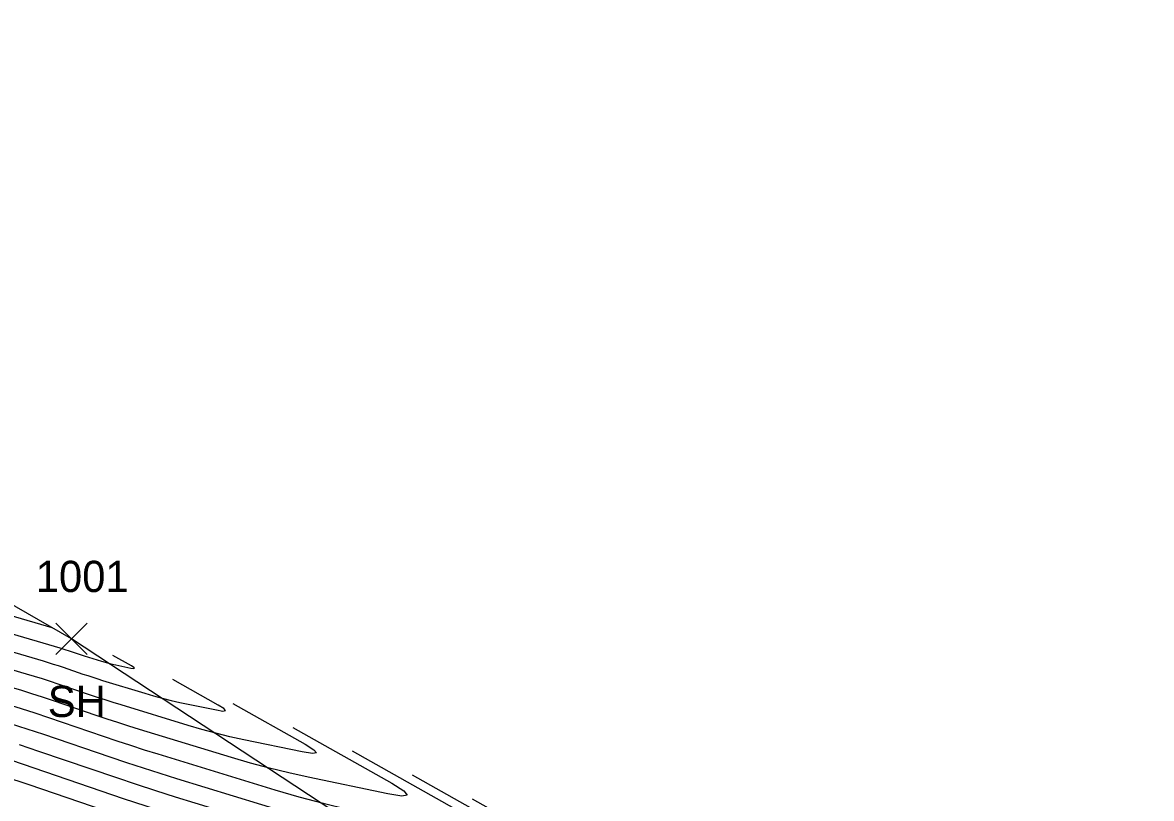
# Model space of a CAD drawing. Extents: x 1650836 to 1652450, y 332578 to 333908.
# Drawn here: x 1651914.6 to 1651986.8, y 332944.5 to 332994.2 of the extents above; entities that cross this region are included whole.
import ezdxf

# ---------------------------------------------------------------- set-up
doc = ezdxf.new("R2010")
doc.units = 0
for name, color, linetype in [('L_A', 7, 'Continuous'), ('L_I', 7, 'Continuous'), ('L_TIC', 7, 'Continuous'), ('LSOGCMA', 7, 'Continuous'), ('LSOGCMI', 7, 'Continuous'), ('LSOGP', 7, 'Continuous')]:
    doc.layers.add(name, color=color, linetype=linetype)

msp = doc.modelspace()

# ---------------------------------------------------------------- linework, layer by layer
at = {"layer": 'L_TIC'}
for points in [[(1651916.714, 332953.706), (1651918.714, 332955.706)], [(1651918.714, 332953.706), (1651916.714, 332955.706)]]:
    msp.add_lwpolyline(points, dxfattribs=at)
at = {"layer": 'LSOGCMA'}
msp.add_lwpolyline([(1651928.045, 332950.575), (1651932.669, 332947.971), (1651933.235, 332947.614), (1651933.392, 332947.411), (1651933.14, 332947.362), (1651932.479, 332947.466), (1651928.759, 332948.246), (1651927.858, 332948.446), (1651926.961, 332948.666), (1651926.069, 332948.906), (1651925.183, 332949.166), (1651920.894, 332950.478), (1651920.388, 332950.635), (1651919.883, 332950.797), (1651919.379, 332950.962), (1651918.877, 332951.131), (1651916.87, 332951.816), (1651916.368, 332951.985), (1651915.863, 332952.148), (1651915.357, 332952.305), (1651914.849, 332952.458), (1651901.898, 332956.265)], dxfattribs=at)
at = {"layer": 'LSOGCMI'}
for points in [[(1651813.439, 332994.157), (1651846.906, 332980.116), (1651850.563, 332978.602), (1651854.233, 332977.123), (1651857.916, 332975.677), (1651861.613, 332974.266), (1651881.787, 332966.674), (1651882.811, 332966.285), (1651883.833, 332965.891), (1651884.852, 332965.49), (1651885.869, 332965.084), (1651889.934, 332963.446), (1651890.954, 332963.049), (1651891.983, 332962.677), (1651893.021, 332962.331), (1651894.068, 332962.009), (1651916.467, 332955.424)], [(1651902.562, 332958.365), (1651916.976, 332954.127), (1651917.107, 332954.088), (1651917.237, 332954.047), (1651917.367, 332954.005), (1651917.496, 332953.962), (1651918.013, 332953.785), (1651918.143, 332953.742), (1651918.272, 332953.699), (1651918.403, 332953.658), (1651918.533, 332953.617), (1651919.638, 332953.279), (1651919.866, 332953.212), (1651920.095, 332953.15), (1651920.326, 332953.094), (1651920.559, 332953.042), (1651921.517, 332952.841), (1651921.687, 332952.814), (1651921.752, 332952.827), (1651921.711, 332952.879), (1651921.566, 332952.971), (1651920.375, 332953.642)], [(1651902.23, 332957.315), (1651915.913, 332953.292), (1651916.232, 332953.197), (1651916.55, 332953.097), (1651916.867, 332952.995), (1651917.183, 332952.889), (1651918.445, 332952.458), (1651918.761, 332952.352), (1651919.078, 332952.248), (1651919.395, 332952.147), (1651919.714, 332952.048), (1651922.41, 332951.223), (1651922.968, 332951.059), (1651923.528, 332950.908), (1651924.092, 332950.77), (1651924.659, 332950.644), (1651926.998, 332950.154), (1651927.413, 332950.088), (1651927.572, 332950.119), (1651927.473, 332950.247), (1651927.117, 332950.471), (1651924.21, 332952.109)], [(1651931.88, 332949.042), (1651938.22, 332945.471), (1651938.997, 332944.981), (1651939.212, 332944.703), (1651938.866, 332944.635), (1651937.96, 332944.779), (1651932.86, 332945.848), (1651931.623, 332946.122), (1651930.393, 332946.424), (1651929.171, 332946.753), (1651927.956, 332947.11), (1651922.075, 332948.909), (1651921.381, 332949.124), (1651920.688, 332949.345), (1651919.998, 332949.572), (1651919.309, 332949.804), (1651916.557, 332950.743), (1651915.868, 332950.974), (1651915.176, 332951.198), (1651914.482, 332951.414), (1651913.786, 332951.623), (1651901.566, 332955.216)], [(1651901.234, 332954.166), (1651912.723, 332950.788), (1651913.608, 332950.523), (1651914.489, 332950.248), (1651915.368, 332949.964), (1651916.244, 332949.671), (1651919.741, 332948.477), (1651920.616, 332948.182), (1651921.493, 332947.894), (1651922.373, 332947.613), (1651923.256, 332947.34), (1651930.728, 332945.053), (1651932.273, 332944.6), (1651933.826, 332944.181), (1651935.389, 332943.798), (1651936.96, 332943.45), (1651943.441, 332942.091), (1651944.593, 332941.909), (1651945.032, 332941.995), (1651944.758, 332942.349), (1651943.772, 332942.971), (1651935.715, 332947.508)], [(1651913.802, 332949.299), (1651914.868, 332948.954), (1651915.931, 332948.598), (1651920.172, 332947.15), (1651921.234, 332946.792), (1651922.299, 332946.443), (1651923.366, 332946.102), (1651924.436, 332945.77), (1651933.501, 332942.997), (1651935.374, 332942.447), (1651937.259, 332941.939), (1651939.154, 332941.474), (1651941.061, 332941.052), (1651948.922, 332939.403), (1651950.319, 332939.182), (1651950.852, 332939.287), (1651950.52, 332939.716), (1651949.323, 332940.471), (1651939.55, 332945.975)], [(1651914.369, 332947.944), (1651915.617, 332947.525), (1651920.604, 332945.823), (1651921.852, 332945.402), (1651923.104, 332944.992), (1651924.359, 332944.591), (1651925.617, 332944.201), (1651936.274, 332940.94), (1651938.476, 332940.294), (1651940.691, 332939.697), (1651942.92, 332939.15), (1651945.161, 332938.654), (1651954.403, 332936.716), (1651956.046, 332936.456), (1651956.672, 332936.578), (1651956.282, 332937.083), (1651954.875, 332937.971), (1651943.385, 332944.441)], [(1651913.869, 332946.934), (1651915.304, 332946.452), (1651921.036, 332944.496), (1651922.471, 332944.012), (1651923.909, 332943.541), (1651925.352, 332943.08), (1651926.798, 332942.632), (1651939.046, 332938.884), (1651941.578, 332938.141), (1651944.124, 332937.455), (1651946.685, 332936.826), (1651949.261, 332936.256), (1651959.884, 332934.028), (1651961.772, 332933.73), (1651962.492, 332933.87), (1651962.043, 332934.451), (1651960.426, 332935.47), (1651947.22, 332942.908)], [(1651913.369, 332945.923), (1651914.991, 332945.379), (1651921.468, 332943.169)]]:
    msp.add_lwpolyline(points, dxfattribs=at)
at = {"layer": 'LSOGP'}
msp.add_lwpolyline([(1651992.258, 332920.35), (1651945.495, 332936.417), (1651917.714, 332954.706), (1651888.541, 332971.502), (1651873.829, 332953.989), (1651868.914, 332946.877), (1651867.782, 332944.676), (1651863.072, 332944.289), (1651861.092, 332941.311), (1651856.451, 332944.302), (1651851.811, 332947.292), (1651847.171, 332950.282), (1651842.53, 332953.273), (1651837.89, 332956.263), (1651833.25, 332959.254), (1651828.61, 332962.244), (1651823.969, 332965.234), (1651818.103, 332969.162), (1651812.237, 332973.09)], dxfattribs=at)

# ---------------------------------------------------------------- texts
at = {"layer": 'L_A'}
msp.add_text('SH', height=2, dxfattribs=at).set_placement((1651916.202, 332949.706))
at = {"layer": 'L_I'}
msp.add_text('1001', height=2, dxfattribs=at).set_placement((1651915.43, 332957.706))

doc.saveas('drawing.dxf')
